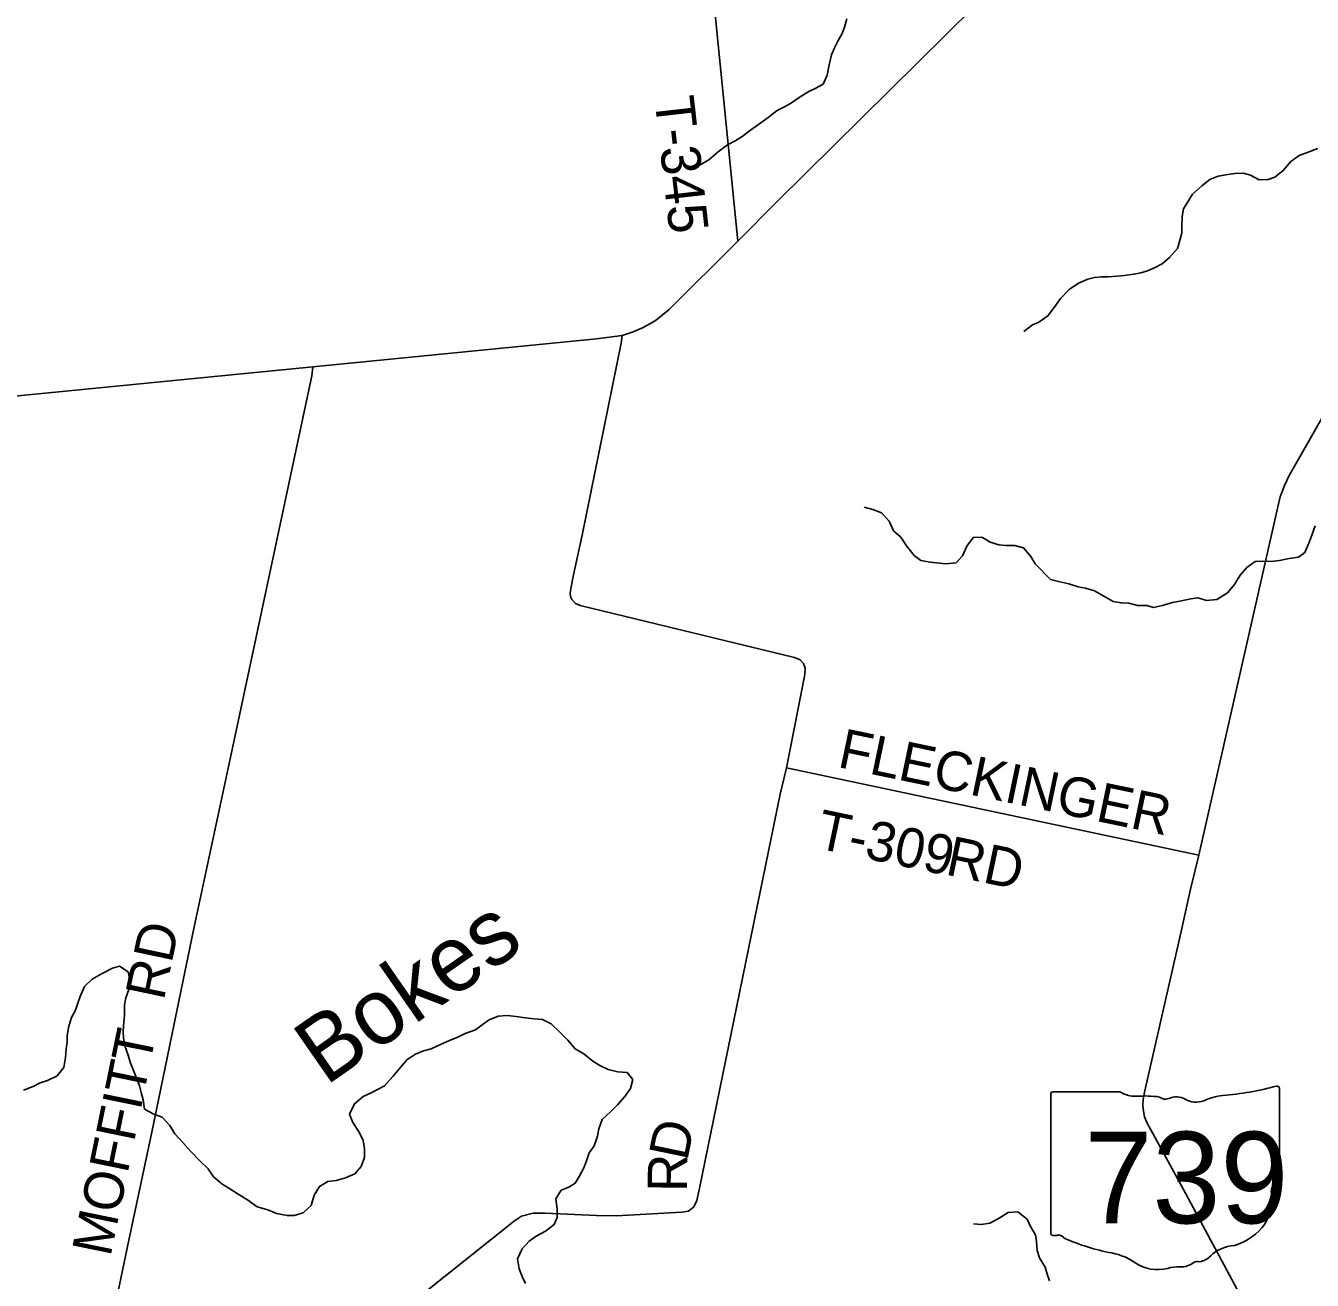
# Model space of a CAD drawing. Extents: x 0 to 34, y 0 to 22.
# Drawn here: x 4.289 to 5.216, y 18.969 to 19.874 of the extents above; entities that cross this region are included whole.
import ezdxf

# ---------------------------------------------------------------- set-up
doc = ezdxf.new("R2010")
doc.units = 0
for name, color, linetype in [('GM_X_County_Road', 7, 'Continuous'), ('GM_X_County_Road_Text', 7, 'Continuous'), ('GM_X_Minor_River', 7, 'Continuous'), ('GM_X_Minor_River_Text', 7, 'Continuous'), ('GM_X_State_Location', 7, 'Continuous'), ('GM_X_State_Route', 7, 'Continuous'), ('GM_X_State_Shield', 7, 'Continuous'), ('GM_X_Township_Road', 7, 'Continuous'), ('GM_X_Township_Road_Text', 7, 'Continuous')]:
    doc.layers.add(name, color=color, linetype=linetype)

msp = doc.modelspace()

# ---------------------------------------------------------------- linework, layer by layer
at = {"layer": 'GM_X_County_Road'}
for points in [[(4.71904, 19.65036), (4.72696, 19.65308), (4.7336, 19.65595), (4.73974, 19.65916), (4.74367, 19.66164), (4.74785, 19.66495), (4.7527, 19.66904), (4.80222, 19.71842), (4.83076, 19.74686), (5.15534, 20.06815)], [(3.22883, 19.5026), (3.77014, 19.55638), (4.18325, 19.59694), (4.49602, 19.62783), (4.70052, 19.64792), (4.71904, 19.65036)], [(4.30942, 18.73967), (4.36352, 18.99822), (4.38, 19.07617), (4.41061, 19.22416), (4.43996, 19.36194), (4.4954, 19.62131), (4.49602, 19.62783)]]:
    msp.add_lwpolyline(points, dxfattribs=at)
at = {"layer": 'GM_X_Minor_River'}
for points in [[(4.88086, 19.87848), (4.87951, 19.87336), (4.8774, 19.86807), (4.87472, 19.86296), (4.87205, 19.85767), (4.86975, 19.85256), (4.8682, 19.84555), (4.86665, 19.83798), (4.86378, 19.83155)], [(4.86378, 19.83155), (4.85809, 19.82836), (4.85335, 19.8263), (4.84652, 19.82179), (4.84026, 19.81747), (4.83533, 19.81485), (4.83059, 19.8126), (4.82414, 19.80752), (4.81731, 19.80245), (4.81142, 19.79831), (4.80554, 19.7938), (4.8008, 19.79098), (4.79492, 19.7878), (4.78809, 19.78272), (4.78144, 19.77707), (4.77519, 19.77332), (4.76893, 19.76994)], [(5.22036, 19.78503), (5.21335, 19.78242), (5.20691, 19.78), (5.20084, 19.77567), (5.19532, 19.76926), (5.18924, 19.76456), (5.18451, 19.76269), (5.17789, 19.76254), (5.17168, 19.766), (5.16639, 19.76736), (5.16034, 19.76702), (5.15542, 19.76648), (5.14842, 19.7652), (5.14236, 19.76277), (5.13667, 19.75826), (5.13002, 19.75223), (5.12353, 19.74165), (5.12256, 19.73615), (5.12233, 19.72895), (5.1223, 19.72421), (5.12057, 19.71815), (5.11903, 19.71303), (5.11332, 19.70662), (5.108, 19.70191), (5.10308, 19.69948), (5.09758, 19.69705), (5.09266, 19.69556), (5.08774, 19.69446), (5.08074, 19.69355), (5.07545, 19.69321), (5.06921, 19.69268), (5.06429, 19.69271), (5.05938, 19.69217), (5.05445, 19.69088), (5.04782, 19.68807), (5.04118, 19.68357), (5.03491, 19.67697), (5.03034, 19.67055), (5.02577, 19.6645), (5.01932, 19.65999), (5.01458, 19.65794), (5.00832, 19.65324)], [(4.95958, 19.48641), (4.95221, 19.4857), (4.94579, 19.4865), (4.94088, 19.4871), (4.93427, 19.48809), (4.92937, 19.49173), (4.92374, 19.49878), (4.91981, 19.50488), (4.91454, 19.50947), (4.91137, 19.51651), (4.90573, 19.52243), (4.89951, 19.52493), (4.89328, 19.52668)], [(5.21828, 19.51321), (5.21597, 19.50639), (5.21386, 19.50071), (5.21099, 19.4939), (5.20624, 19.49052), (5.19963, 19.48961), (5.19262, 19.48814), (5.18657, 19.48742), (5.18053, 19.48765), (5.17504, 19.48749), (5.16916, 19.48317), (5.16441, 19.4777), (5.16021, 19.47089), (5.15507, 19.46486), (5.14749, 19.45997), (5.14011, 19.45926), (5.1337, 19.4612), (5.12878, 19.46066), (5.12197, 19.459), (5.11554, 19.4579), (5.10834, 19.45567), (5.10191, 19.45438), (5.097, 19.45574), (5.09039, 19.45579), (5.08397, 19.45734), (5.07868, 19.45757), (5.07283, 19.45855), (5.05926, 19.46623), (5.05285, 19.46817), (5.04756, 19.46915), (5.04077, 19.47128), (5.03435, 19.47284), (5.02756, 19.47459), (5.01666, 19.48567), (5.01347, 19.491), (5.00822, 19.49729), (5.00199, 19.49904), (4.99537, 19.49908), (4.99027, 19.49949), (4.98424, 19.50143), (4.97858, 19.50469), (4.97216, 19.50511), (4.96721, 19.4985), (4.96415, 19.4915), (4.95958, 19.48641)], [(4.588, 19.13935), (4.58137, 19.13616), (4.57588, 19.13487), (4.57001, 19.13244), (4.56394, 19.1285), (4.55861, 19.12227), (4.55366, 19.11624), (4.54777, 19.10963), (4.54303, 19.1072), (4.5381, 19.10458), (4.53223, 19.10177), (4.52615, 19.09669), (4.52252, 19.08912), (4.52494, 19.08304), (4.52887, 19.07694), (4.53224, 19.07028), (4.53334, 19.06439), (4.5333, 19.05794), (4.53081, 19.05132), (4.52624, 19.04604), (4.51961, 19.04324), (4.5128, 19.04138), (4.50674, 19.04048), (4.50086, 19.0371), (4.49705, 19.03068), (4.49474, 19.02329), (4.48904, 19.01802), (4.4826, 19.01616), (4.4775, 19.0162), (4.46995, 19.01757), (4.46354, 19.02008), (4.4558, 19.02241), (4.44884, 19.02738), (4.44225, 19.03141), (4.43735, 19.03448), (4.43057, 19.03888), (4.42455, 19.04404), (4.42062, 19.04976), (4.4146, 19.05549), (4.40821, 19.06217), (4.40239, 19.06866), (4.39657, 19.07495), (4.39301, 19.08105), (4.38756, 19.08696), (4.38134, 19.08909), (4.37475, 19.09273), (4.37365, 19.09957), (4.37236, 19.1047), (4.37106, 19.10945), (4.36883, 19.11572), (4.36622, 19.12181), (4.36435, 19.12657), (4.36306, 19.1317), (4.36064, 19.13835), (4.35954, 19.14386), (4.35938, 19.14898), (4.35979, 19.15543), (4.3602, 19.16055), (4.36024, 19.16795), (4.36121, 19.17287), (4.36332, 19.17893), (4.36449, 19.18499), (4.36302, 19.19164), (4.3568, 19.19585), (4.35169, 19.19437), (4.34373, 19.19025), (4.33709, 19.18631), (4.3314, 19.18103), (4.32833, 19.17403), (4.3266, 19.16911), (4.32488, 19.164), (4.3222, 19.15871), (4.31989, 19.15151), (4.3191, 19.14564), (4.31889, 19.1409), (4.31829, 19.13616), (4.31769, 19.1299), (4.31652, 19.1227), (4.31176, 19.11666), (4.30475, 19.1133), (4.29964, 19.11181), (4.29452, 19.109), (4.28751, 19.10639)], [(4.64939, 18.9671), (4.64677, 18.97205), (4.64472, 18.97756), (4.64344, 18.98497), (4.64689, 18.99215), (4.65202, 18.99762), (4.65695, 19.00119), (4.66359, 19.00475), (4.67004, 19.00964), (4.67215, 19.01456), (4.672, 19.02101), (4.67109, 19.02803), (4.6751, 19.03446), (4.6804, 19.03651), (4.68514, 19.03932), (4.688, 19.04424), (4.69125, 19.05048), (4.69317, 19.05559), (4.69528, 19.06126), (4.69871, 19.06636), (4.70121, 19.07336), (4.70218, 19.07848), (4.70449, 19.08529), (4.71076, 19.09094), (4.71551, 19.09585), (4.72084, 19.10188), (4.72484, 19.10774), (4.72658, 19.11417), (4.72245, 19.11913), (4.71583, 19.11974), (4.70885, 19.12131), (4.70282, 19.12419), (4.69773, 19.12726), (4.69134, 19.13261), (4.68512, 19.13626), (4.67968, 19.14255), (4.67423, 19.14809), (4.66784, 19.1542), (4.66162, 19.15746), (4.65538, 19.15788), (4.64915, 19.15849), (4.64254, 19.15948), (4.63612, 19.16028), (4.6295, 19.15976), (4.62306, 19.15714), (4.61813, 19.15357), (4.6132, 19.15), (4.60581, 19.1472), (4.60107, 19.14476), (4.59444, 19.14215), (4.588, 19.13935)], [(5.02681, 18.96905), (5.02532, 18.9738), (5.02384, 18.97874), (5.01972, 18.98559), (5.01805, 18.99091), (5.01752, 18.99699), (5.01679, 19.00211), (5.01324, 19.00821), (5.01081, 19.01334), (5.00404, 19.0187), (4.99723, 19.01817), (4.99059, 19.01423), (4.98396, 19.01067), (4.9779, 19.00957), (4.97205, 19.00998)]]:
    msp.add_lwpolyline(points, dxfattribs=at)
at = {"layer": 'GM_X_State_Route'}
for points in [[(5.1429, 18.99854), (5.12344, 19.03494), (5.09717, 19.08257), (5.09547, 19.08712), (5.09452, 19.0914), (5.09408, 19.09547), (5.09432, 19.09967), (5.09543, 19.10489), (5.12169, 19.2208), (5.12854, 19.25123), (5.13448, 19.27587), (5.18923, 19.51732), (5.19136, 19.52682), (5.19318, 19.53402), (5.19619, 19.54232), (5.19967, 19.54952), (5.2382, 19.6171)], [(5.20657, 18.66802), (5.20883, 18.73226), (5.20928, 18.76094), (5.20866, 18.76845), (5.21114, 18.81116), (5.21219, 18.84622), (5.2121, 18.8612), (5.21152, 18.87032), (5.20959, 18.87794), (5.20637, 18.8873), (5.19981, 18.90014), (5.18682, 18.92221), (5.16737, 18.95295), (5.14907, 18.98699), (5.1429, 18.99854)]]:
    msp.add_lwpolyline(points, dxfattribs=at)
at = {"layer": 'GM_X_State_Shield'}
for p, q in [((5.02776, 19.1035), (5.02776, 19.00344)), ((5.07765, 19.10522), (5.02939, 19.10522)), ((5.19256, 19.05536), (5.19256, 19.1077)), ((5.19254, 19.05537), (5.19256, 19.05536))]:
    msp.add_line(p, q, dxfattribs=at)
for centre, major_axis, start_param, end_param in [((5.13386, 19.24163), (0.17476, 0), 4.814394, 5.042369), ((5.19073, 19.10792), (0.00183, 0), 6.141152, 7.989035), ((5.02965, 19.10371), (0.00191, 0), 1.712693, 3.28349), ((5.08914, 19.11683), (0.01852, 0), 4.042523, 4.731795), ((5.09528, 19.04904), (0.06648, 0), 1.404758, 1.657858), ((5.11037, 19.10423), (0.00534, 0), 3.836095, 5.185415), ((5.11821, 19.09266), (0.01111, 0), 0.950623, 2.079405), ((5.13255, 19.10853), (0.01336, 0), 4.081561, 5.145723), ((5.15615, 19.07466), (0.03516, 0), 1.699011, 2.107814), ((5.19213, 19.05151), (0.00284, 0), 1.883978, 3.671073), ((5.1906, 19.05515), (0.00196, 0), 5.05454, 6.418171), ((5.17407, 19.0449), (0.01704, 0), 5.934695, 6.695948), ((5.19913, 19.03345), (0.0124, 0), 2.387724, 3.262537), ((5.14365, 19.02679), (0.04371, 0), 5.101752, 6.440018), ((5.02967, 19.00322), (0.00193, 0), 3.00124, 4.508301), ((5.02996, 19.01345), (0.0147, 0), 4.665946, 4.897461), ((5.03297, 18.99766), (0.0053, 0), 0.519207, 1.627899), ((5.09988, 19.08756), (0.1262, 0), 4.195997, 4.488961), ((5.06226, 18.95848), (0.03949, 0), 0.823519, 1.323587), ((5.16208, 18.97534), (0.02394, 0), 1.647645, 2.488434), ((5.10496, 18.99717), (0.02506, 0), 4.026481, 4.996735), ((5.11944, 18.96257), (0.02059, 0), 1.495662, 1.94098), ((5.12127, 18.98967), (0.01335, 0), 4.691044, 5.507374), ((5.13335, 18.97998), (0.00376, 0), 1.147584, 2.315152), ((5.13174, 18.99374), (0.01412, 0), 4.937069, 5.64225)]:
    msp.add_ellipse(centre, major_axis=major_axis, ratio=0.8, start_param=start_param, end_param=end_param, dxfattribs=at)
at = {"layer": 'GM_X_Township_Road'}
msp.add_line((4.83737, 19.33874), (5.13448, 19.27587), dxfattribs=at)
for points in [[(4.80222, 19.71842), (4.77835, 19.95912), (4.77813, 19.96233), (4.7771, 19.96468), (4.77546, 19.96691), (4.77351, 19.96844), (4.7702, 19.96968), (4.76631, 19.96988), (4.67408, 19.95974), (4.6704, 19.95928), (4.66787, 19.95942), (4.66564, 19.95985), (4.66381, 19.96048), (4.66219, 19.96141), (4.66081, 19.96276), (4.65954, 19.96448), (4.65864, 19.96651), (4.658, 19.96948), (4.6576, 19.97193), (4.65615, 19.98809), (4.64697, 20.0779), (4.64533, 20.09214), (4.64465, 20.10304), (4.61912, 20.35045)], [(4.83737, 19.33874), (4.85066, 19.40595), (4.85081, 19.41066), (4.84959, 19.41406), (4.8471, 19.41656), (4.84314, 19.41834), (4.69553, 19.45398), (4.68861, 19.45576), (4.68537, 19.45711), (4.6826, 19.45996), (4.68177, 19.46201), (4.68149, 19.4647), (4.68188, 19.46799), (4.68398, 19.4778), (4.69007, 19.50652), (4.71819, 19.64476), (4.71904, 19.65036)], [(4.51872, 18.79907), (4.54994, 18.93213), (4.55168, 18.93725), (4.55456, 18.94193), (4.5585, 18.94615), (4.64136, 19.01214), (4.64645, 19.01549), (4.65489, 19.01785), (4.66357, 19.01785), (4.70053, 19.01598), (4.71467, 19.01586), (4.7619, 19.0184), (4.76679, 19.01918), (4.77071, 19.02225), (4.7727, 19.02684), (4.77443, 19.03453), (4.83281, 19.31971), (4.83737, 19.33874)]]:
    msp.add_lwpolyline(points, dxfattribs=at)

# ---------------------------------------------------------------- texts
at = {"layer": 'GM_X_County_Road_Text'}
for s, rotation, p in [('RD', 78.0099, (4.38854, 19.17044)), ('MOFFITT', 78.40748, (4.35017, 18.98574))]:
    msp.add_text(s, height=0.028409, rotation=rotation, dxfattribs=at).set_placement(p)
at = {"layer": 'GM_X_Minor_River_Text'}
msp.add_text('Bokes', height=0.047353, rotation=34.80529, dxfattribs=at).set_placement((4.50517, 19.10905))
at = {"layer": 'GM_X_State_Location'}
for s, p in [('s', (5.10831, 19.04681)), ('r', (5.1083, 19.04681))]:
    msp.add_text(s, height=0.0000947, dxfattribs=at).set_placement(p)
msp.add_text('739', height=0.0000947, rotation=0.00001, dxfattribs=at).set_placement((5.07488, 19.03992))
at = {"layer": 'GM_X_State_Shield'}
msp.add_text('739', height=0.065918, dxfattribs=at).set_placement((5.052, 19.01049))
at = {"layer": 'GM_X_Township_Road_Text'}
for s, height, rotation, p in [('T-345', 0.028409, 276.46366, (4.74213, 19.82131)), ('FLECKINGER', 0.028409, 348.21379, (4.87341, 19.33947)), ('T-309', 0.028409, 348.14032, (4.85766, 19.28111)), ('RD', 0.028409, 348.11018, (4.95107, 19.262)), ('D', 0.02841, 78.33215, (4.76579, 19.05486)), ('R', 0.02841, 89.46136, (4.76572, 19.03298))]:
    msp.add_text(s, height=height, rotation=rotation, dxfattribs=at).set_placement(p)

doc.saveas('drawing.dxf')
